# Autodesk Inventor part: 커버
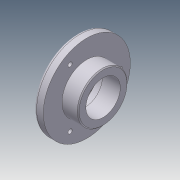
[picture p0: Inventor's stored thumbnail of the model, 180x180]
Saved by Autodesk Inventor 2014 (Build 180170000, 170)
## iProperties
Company: 한국ATC센터
Created: 2014-10
Part Number: 커버
Document SubType Name: Modeling
Designer: 한국ATC센터
Density: 2.71 g/cm^3
Material: 알루미늄-6061
Mass: 189.969 g
Surface Area: 197.235 cm^2
Volume: 70.0991 cm^3
Appearance: 알루미늄 - 평지
Author: KYOUNG IL JANG
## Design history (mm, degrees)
sketch "스케치1"
  geometry: L1 (-13.5, 0)-(13.5, 0); L2 (-13.5, 0)-(-13.5, 45.5); L3 (-13.5, 45.5)-(-3.5, 45.5); L4 (-3.5, 45.5)-(-3.5, 26); L5 (-3.5, 26)-(13.5, 26); L6 (13.5, 26)-(13.5, 0); 2 further points
  constraints: 12 end point, 3 parallel, 2 perpendicular, 1 coincident, 1 horizontal, 1 midpoint
  dimensions: "d0" = 27 distance of L1.start L1.end; "d1" = 91 diameter of L3 L1; "d2" = 52 diameter of L5 L1; "d3" = 10 distance of L2.end L3.end
revolve "회전1" sketch "스케치1" stored, may be unused: angle "d4" = 90 deg
hole "구멍1" diameter "d7" = 36; stored, may be unused: countersink angle "d11" = 90 deg, drill point angle "d13" = 118 deg; dims "d5" = 10, "d6" = 10, "d8" = 6, "d9" = 40, "d10" = 8.3, "d12" = 8
sketch "스케치2"
  geometry: 2 further points
  constraints: 1 vertical alignment
  dimensions: "d14" = 35 distance of point (0, 0) point (0, 35)
hole "구멍2" sketch "스케치2" at (0, 35) diameter "d15" = 4.5; stored, may be unused: countersink angle "d19" = 90 deg, drill point angle "d21" = 118 deg; dims "d16" = 6, "d17" = 8, "d18" = 4.4, "d20" = 8
chamfer "모따기1" distance "d25" = 0.8; stored, may be unused: second distance "d26" = 2, angle "d27" = 30 deg
fillet "모깎기1" dims "d28" = 0.1, "d29" = 3
chamfer "모따기2" distance "d30" = 1; stored, may be unused: second distance "d31" = 2, angle "d32" = 30 deg
node "솔리드1"
pattern_circular "원형 패턴1" dims angle "d23" = 360 deg
